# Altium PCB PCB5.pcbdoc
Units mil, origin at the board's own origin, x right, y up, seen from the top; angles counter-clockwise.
Board outline 7370 x 5003.1 mil, 2 copper layers (Top Layer, Bottom Layer); 30 components, 59 nets, 149 pads, 1 vias.
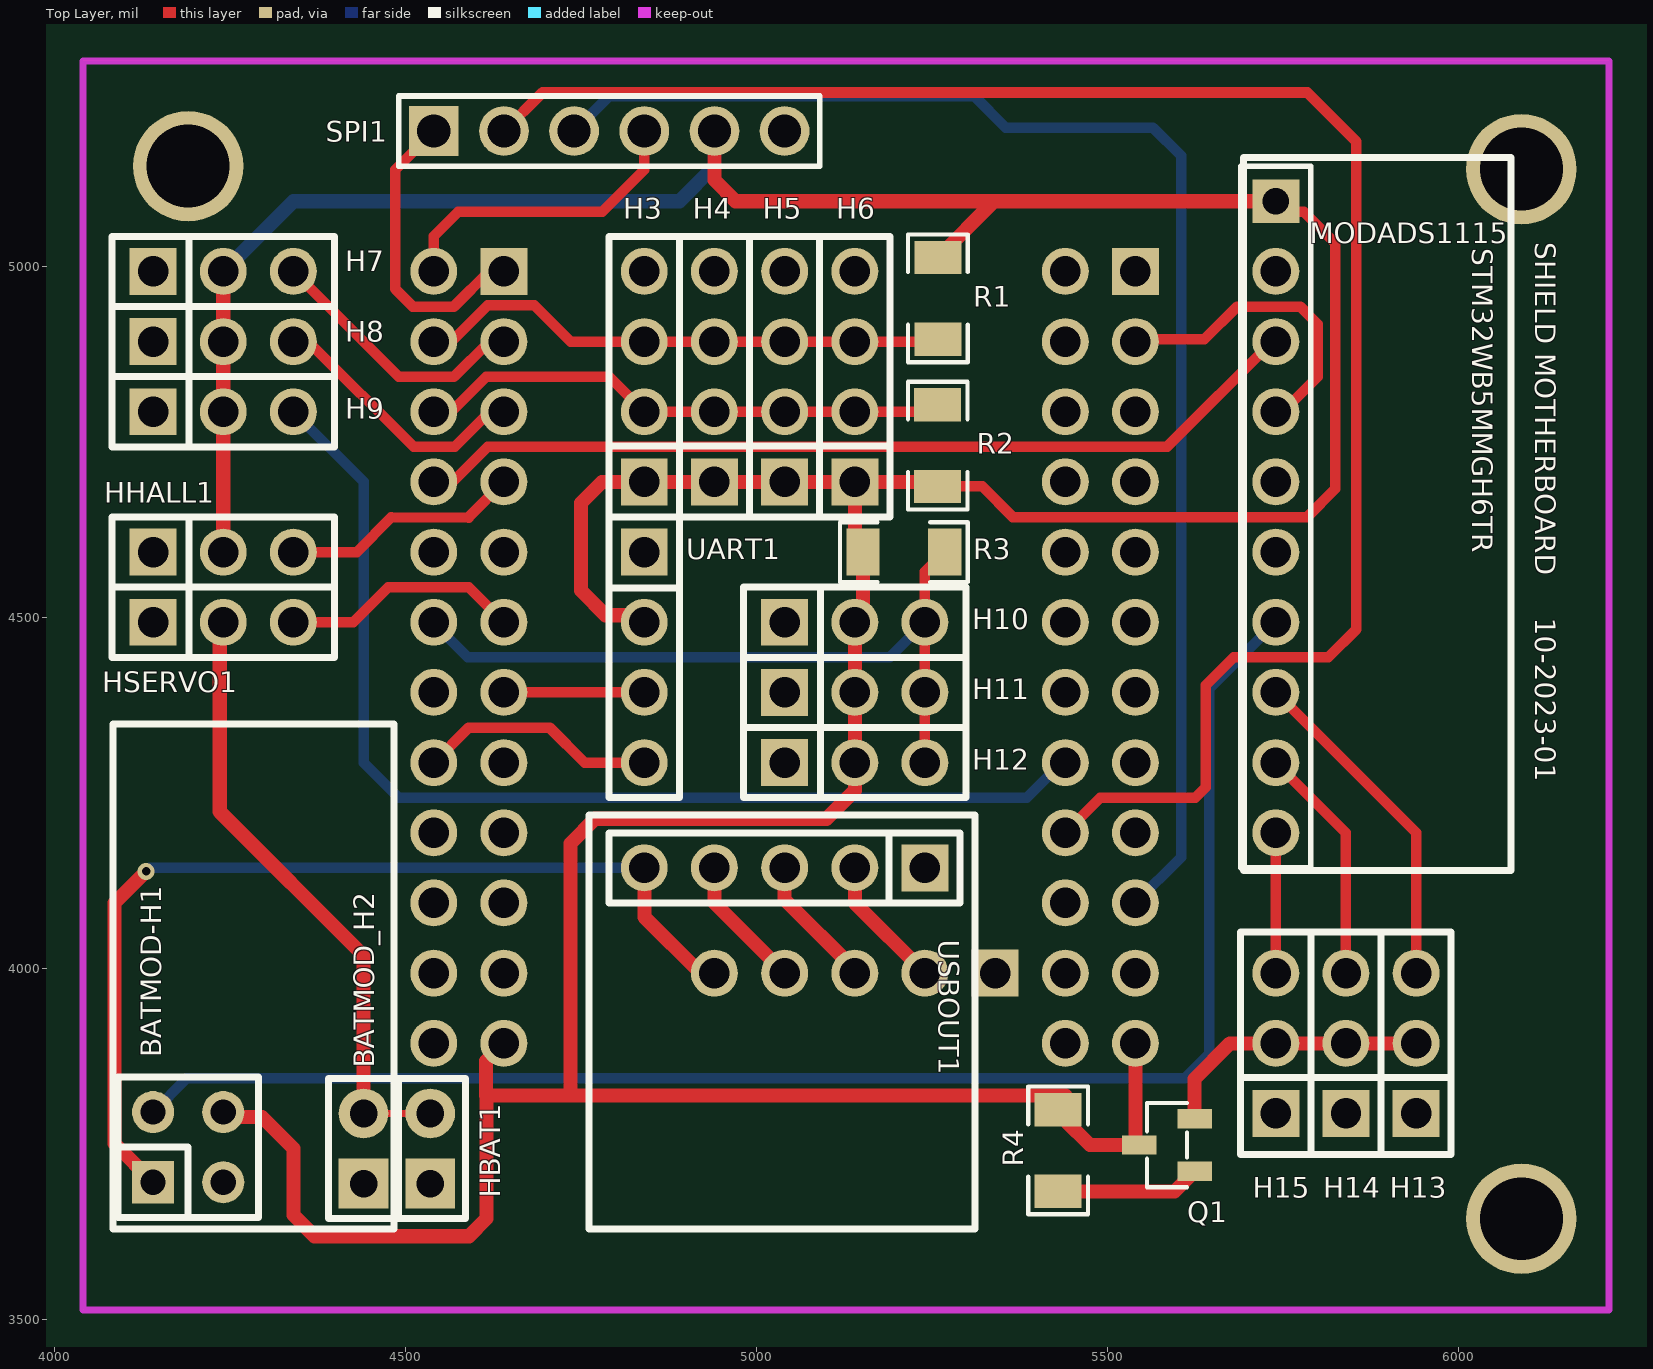
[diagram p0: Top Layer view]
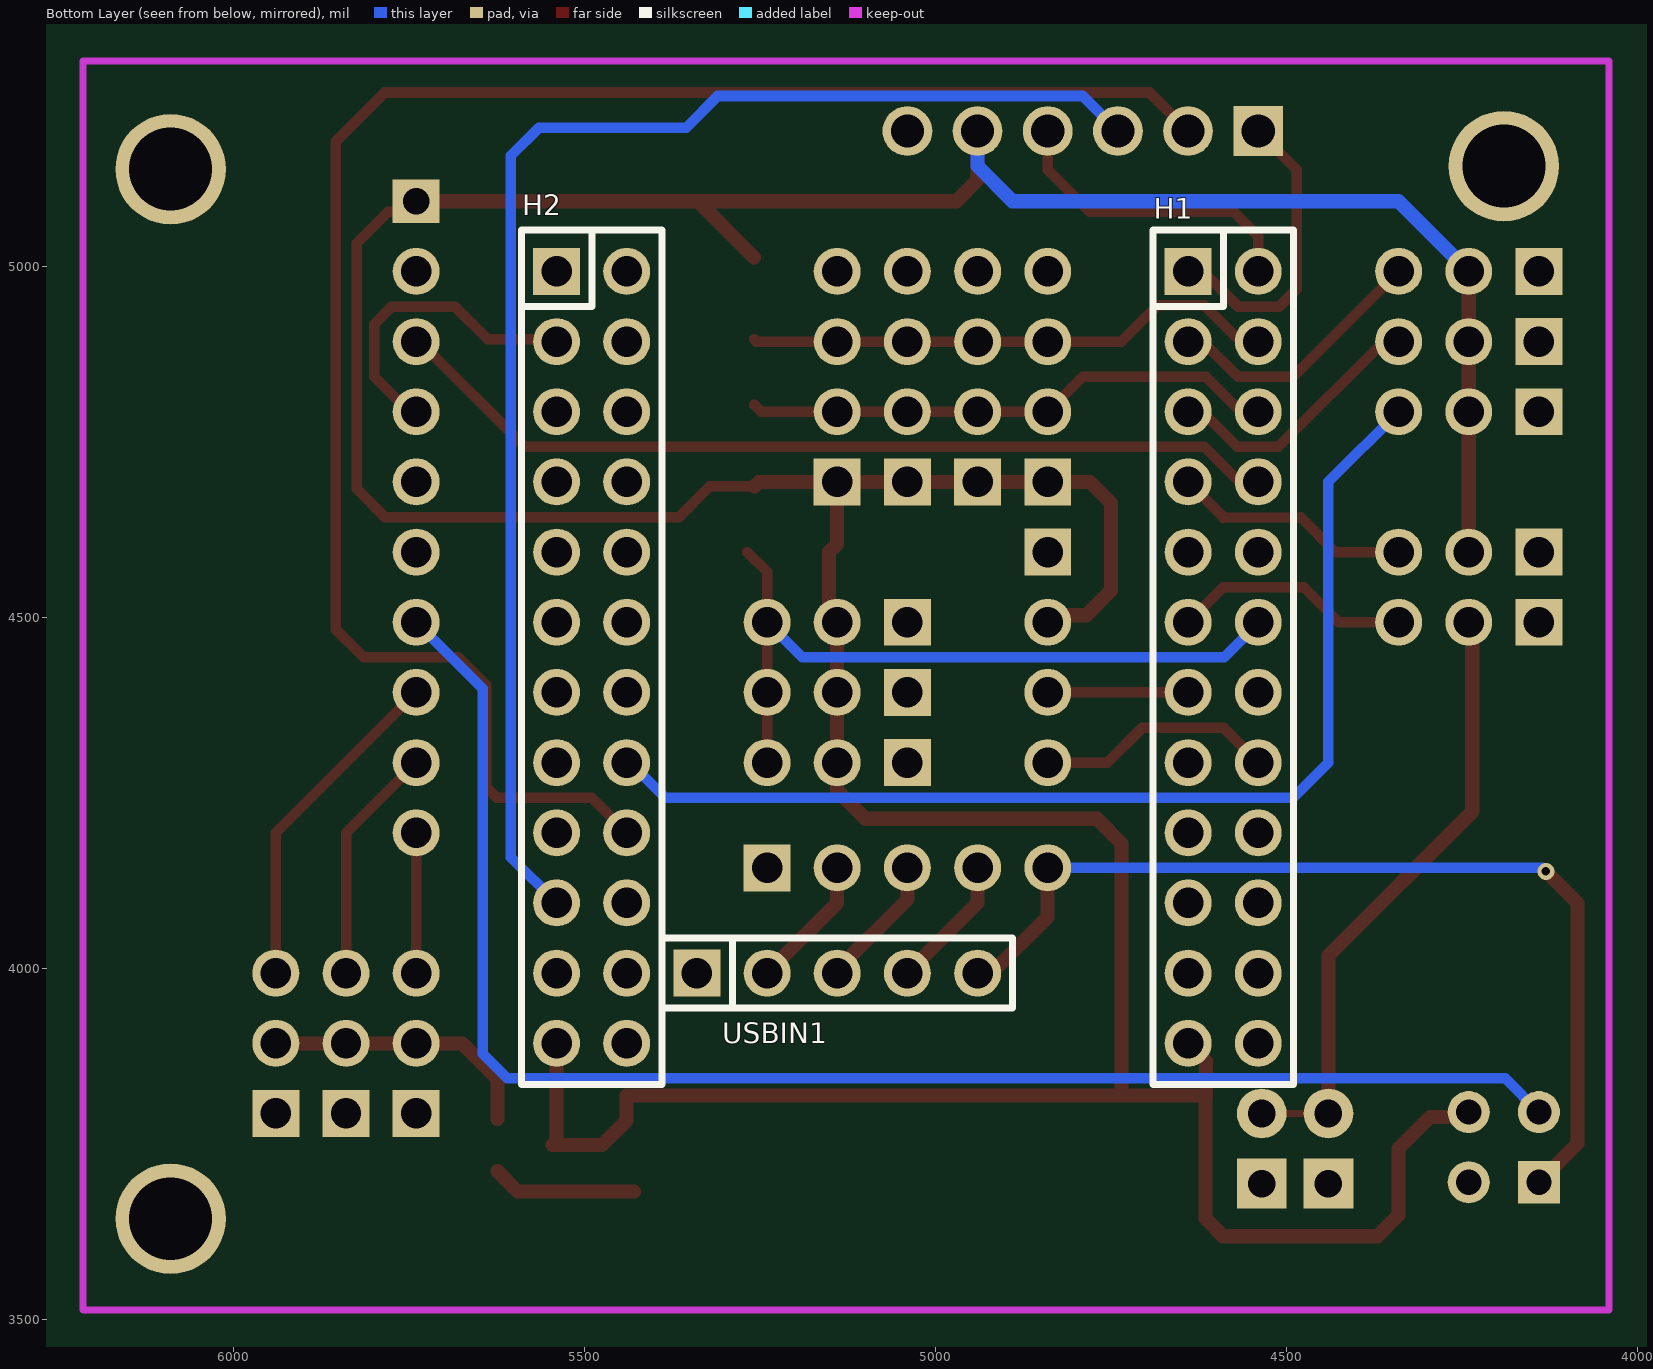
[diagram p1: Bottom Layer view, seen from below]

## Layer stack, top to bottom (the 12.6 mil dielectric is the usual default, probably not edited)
Top Layer: signal copper (thickness not stored)
Dielectric: dielectric 12.6, FR-4, Dk 4.8
Bottom Layer: signal copper (thickness not stored)

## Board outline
10120,2750 2750,2750 2750,7753.1 10120,7753.1

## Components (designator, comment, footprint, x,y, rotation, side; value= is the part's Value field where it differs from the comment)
BATMOD-H1 "HDR-M_2.54_2x2" HDR-TH_4P-P2.54-V-M-R2-C2-S2.54-1 4190,3745.01 r0 top
BATMOD_H2 "HDR-M_2.54_1x2P" HDR-TH_2P-P2.54-V-M-1 4440,3743.1 r90 top
H1 "PZ254-2-12-Z-8.5" HDR-TH_24P-P2.54-V-M-R2-C12-S2.54 4590,4443.1 r270 bottom
H2 "PZ254-2-12-Z-8.5" HDR-TH_24P-P2.54-V-M-R2-C12-S2.54 5490,4443.1 r270 bottom
H3 "HDR-M_2.54_1x4P" HDR-TH_4P-P2.54-V-M 4840,4843.1 r90 top
H4 "HDR-M_2.54_1x4P" HDR-TH_4P-P2.54-V-M 4940,4843.1 r90 top
H5 "HDR-M_2.54_1x4P" HDR-TH_4P-P2.54-V-M 5040,4843.11 r90 top
H6 "HDR-M_2.54_1x4P" HDR-TH_4P-P2.54-V-M 5140,4843.1 r90 top
H7 "HDR-M_2.54_1x3P" HDR-TH_3P-P2.54-V-M 4240,4993.1 r0 top
H8 "HDR-M_2.54_1x3P" HDR-TH_3P-P2.54-V-M 4240,4893.1 r0 top
H9 "HDR-M_2.54_1x3P" HDR-TH_3P-P2.54-V-M 4240,4793.1 r0 top
H10 "HDR-M_2.54_1x3P" HDR-TH_3P-P2.54-V-M 5140,4493.1 r0 top
H11 "HDR-M_2.54_1x3P" HDR-TH_3P-P2.54-V-M 5140,4393.1 r0 top
H12 "HDR-M_2.54_1x3P" HDR-TH_3P-P2.54-V-M 5140,4293.1 r0 top
H13 "HDR-M_2.54_1x3P" HDR-TH_3P-P2.54-V-M 5940,3893.1 r90 top
H14 "HDR-M_2.54_1x3P" HDR-TH_3P-P2.54-V-M 5840,3893.1 r90 top
H15 "HDR-M_2.54_1x3P" HDR-TH_3P-P2.54-V-M 5740,3893.1 r90 top
HBAT1 "HDR-M_2.54_1x2P" HDR-TH_2P-P2.54-V-M-1 4535,3743.1 r90 top
HHALL1 "HDR-M_2.54_1x3P" HDR-TH_3P-P2.54-V-M 4240,4593.1 r0 top
HSERVO1 "HDR-M_2.54_1x3P" HDR-TH_3P-P2.54-V-M 4240,4493.1 r0 top
MODADS1115 "HDR-M_2.54_1x10P" hdr-th_10p-p2.54-v-m-1 5740,4643.1 r270 top
Q1 "CJ2301" SOT-23-3_L2.9-W1.3-P1.90-LS2.4-BR 5585,3748.1 r0 top
R1 "Res_1206" R1206 5258.4,4954.64 r270 top
R2 "Res_1206" R1206 5258.22,4744.88 r90 top
R3 "Res_1206" R1206 5210,4593.1 r180 top
R4 "Res_1206" R1206 5429.84,3740.32 r90 top
SPI1 "HDR-M_2.54_1x6P" HDR-TH_6P-P2.54-V-M-1 4790,5193.1 r0 top
UART1 "HDR-M_2.54_1x4P" HDR-TH_4P-P2.54-V-M 4840,4443.1 r270 top
USBIN1 "HDR-M_2.54_1x5P" HDR-TH_5P-P2.54-V-M 5140,3993.1 r180 bottom
USBOUT1 "HDR-M_2.54_1x5P" HDR-TH_5P-P2.54-V-M 5040,4143.1 r180 top

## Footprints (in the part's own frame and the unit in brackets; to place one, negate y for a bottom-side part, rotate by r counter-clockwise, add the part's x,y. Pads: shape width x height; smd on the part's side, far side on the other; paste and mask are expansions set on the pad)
HDR-TH_2P-P2.54-V-M-1 [mm]
  rect 1.8x1.8 hole 1: 1(-1.27,0)
  round 1.8 hole 1: 2(1.27,0)
  silkscreen extent -2.54,-1.27 2.54,1.27
HDR-TH_3P-P2.54-V-M [mm]
  rect 1.7x1.7 hole 1.1: 1(-2.54,0)
  round 1.7 hole 1.1: 2(0,0) 3(2.54,0)
  silkscreen extent -4.02,-1.27 4.02,1.27
HDR-TH_4P-P2.54-V-M [mm]
  rect 1.7x1.7 hole 1.1: 1(-3.81,0)
  round 1.7 hole 1.1: 2(-1.27,0) 3(1.27,0) 4(3.81,0)
  silkscreen extent -5.08,-1.27 5.08,1.27
HDR-TH_4P-P2.54-V-M-R2-C2-S2.54-1 [mil]
  rect 60x60 hole 36: 1(-50,-50)
  round 60 hole 36: 2(-50,50) 3(50,-50) 4(50,50)
  silkscreen extent -100,-100 100,100
HDR-TH_5P-P2.54-V-M [mm]
  rect 1.7x1.7 hole 1.1: 1(-5.08,0)
  round 1.7 hole 1.1: 2(-2.54,0) 3(0,0) 4(2.54,0) 5(5.08,0)
  silkscreen extent -6.35,-1.27 6.35,1.27
HDR-TH_6P-P2.54-V-M-1 [mm]
  rect 1.8x1.8 hole 1.2: 1(-6.35,0)
  round 1.8 hole 1.2: 2(-3.81,0) 3(-1.27,0) 4(1.27,0) 5(3.81,0) 6(6.35,0)
  silkscreen extent -7.62,-1.27 7.62,1.27
hdr-th_10p-p2.54-v-m-1 [mm]
  rect 1.575x1.7 hole 0.945: 1(-11.43,0)
  round 1.7 hole 1.1: 2(-8.89,0) 3(-6.35,0) 4(-3.81,0) 5(-1.27,0) 6(1.27,0) 7(3.81,0) 8(6.35,0) 9(8.89,0) 10(11.43,0)
  silkscreen extent -12.7,-1.27 12.7,1.27
HDR-TH_24P-P2.54-V-M-R2-C12-S2.54 [mm]
  rect 1.7x1.7 hole 1.1: 1(-13.97,-1.27)
  round 1.7 hole 1.1: 2(-13.97,1.27) 3(-11.43,-1.27) 4(-11.43,1.27) 5(-8.89,-1.27) 6(-8.89,1.27) 7(-6.35,-1.27) 8(-6.35,1.27) 9(-3.81,-1.27) 10(-3.81,1.27) 11(-1.27,-1.27) 12(-1.27,1.27) 13(1.27,-1.27) 14(1.27,1.27) 15(3.81,-1.27) 16(3.81,1.27) 17(6.35,-1.27) 18(6.35,1.27) 19(8.89,-1.27) 20(8.89,1.27) 21(11.43,-1.27) 22(11.43,1.27) 23(13.97,-1.27) 24(13.97,1.27)
  silkscreen extent -15.47,-2.54 15.47,2.54
R1206 [mil]
  rect 47.54x66.97 smd: 1(-58.22,0) 2(58.22,0)
  silkscreen extent -91,-42 91,42
SOT-23-3_L2.9-W1.3-P1.90-LS2.4-BR [mm]
  rect 1.25x0.7 smd: 1(1,-0.95) 2(1,0.95) 3(-1,0)
  silkscreen extent -0.73,-1.53 0.73,1.53

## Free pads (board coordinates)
  round 157.48 hole 118.11: 1(4190,5143.1) 1(6090,3643.1)
  round 157.5 hole 118.11: 1(6090,5138.81)

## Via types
v1: diameter 24.02, hole 12.01, Top Layer to Bottom Layer, 1 vias

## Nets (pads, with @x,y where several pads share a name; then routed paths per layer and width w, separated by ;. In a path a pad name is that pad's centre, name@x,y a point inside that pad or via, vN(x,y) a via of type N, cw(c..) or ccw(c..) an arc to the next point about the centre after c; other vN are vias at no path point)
AIN1: H13.3 MODADS1115.8 | length 482.8
  Top Layer w15: MODADS1115.8 5940,4193.1 H13.3
AIN2: H14.3 MODADS1115.9 | length 341.4
  Top Layer w15: MODADS1115.9 5840,4193.1 H14.3
AIN3: H15.3 MODADS1115.10 | length 200
  Top Layer w15: H15.3 MODADS1115.10
ALERT: MODADS1115.6
BOOT0: H2.15
CMDVCAPT: Q1.1 R4.1 | length 206.4
  Top Layer w20: R4.1 5595.77,3682.1 Q1.1
D+: USBIN1.3 USBOUT1.3 | length 191.4
  Top Layer w20: USBOUT1.3 5040,4098.1 5140,3998.1 USBIN1.3
D-: USBIN1.4 USBOUT1.4 | length 191.4
  Top Layer w20: USBOUT1.4 4940,4093.1 USBIN1.4
GND: BATMOD-H1.3 BATMOD_H2.1 H1.24 H2.24 H3.4 H4.4 H5.4 H6.4 H7.1 H8.1 H9.1 H10.1 H11.1 H12.1 H13.1 H14.1 H15.1 HBAT1.1 HHALL1.1 HSERVO1.1 MODADS1115.2 MODADS1115.5 pad.1 SPI1.6 UART1.1 USBIN1.1 USBOUT1.1
I2C1_SCL: H1.8 MODADS1115.3 | length 1286.2
  Top Layer w15: H1.8 4544.02,4689.08 4562.88,4689.08 4616.89,4743.1 5585,4743.1 5735,4893.1 MODADS1115.3
I2C1_SDA: H2.3 MODADS1115.4 | length 446.8
  Top Layer w15: H2.3 5543.11,4896.21 5638.11,4896.21 5685,4943.1 5775,4943.1 5800,4918.1 5800,4843.1 5750,4793.1 MODADS1115.4
I2C3_SCL: H1.4 H3.3 H4.3 H5.3 H6.3 R1.2 | length 762.8
  Top Layer w15: H1.4 4565,4893.1 4616.95,4945.05 4683.05,4945.05 4735,4893.1 H3.3 H4.3 H5.3 H6.3 5255.07,4893.1 R1.2
I2C3_SDA: H1.6 H3.2 H4.2 H5.2 H6.2 R2.2 | length 763.8
  Top Layer w15: H1.6 4565,4793.1 4615,4843.1 4790,4843.1 H3.2 H4.2 H5.2 H6.2 5248.22,4793.1 R2.2
IO: USBIN1.2 USBOUT1.2 | length 191.4
  Top Layer w20: USBOUT1.2 5140,4093.1 USBIN1.2
LED: H2.21
LPTIM1_IN1: H2.1
LPTIM2_IN1: H2.16 H9.3 | length 1577.8
  Bottom Layer w15: H9.3 4440,4693.1 4440,4293.1 4490,4243.1 5385,4243.1 H2.16@5435,4293.1
LPUART1_RX: H1.16 UART1.4 | length 341.4
  Top Layer w15: H1.16 4590,4343.1 4705,4343.1 4755,4293.1 UART1.4
LPUART1_TX: H1.13 UART1.3 | length 205
  Top Layer w15: H1.13@4635,4393.1 UART1.3
NRST: H2.17
PA0: H2.22
PA1: H1.22
PA8: H1.17
PA15: H2.10
PB0/ONEWIRE: H1.12 H10.3 H11.3 H12.3 R3.1 | length 1053.9
  Top Layer w15: H12.3 H11.3 H10.3 5240,4564.88 R3.1
  Bottom Layer w15: H1.12 4540,4491.7 4588.6,4443.1 5190,4443.1 H10.3
PB1: H1.11 HSERVO1.3 | length 341.4
  Top Layer w15: HSERVO1.3 4425,4493.1 4475,4543.1 4590,4543.1 H1.11
PB2: H1.15
PB12: H1.10
PB15: H1.5 H8.3 | length 382.8
  Top Layer w15: H8.3 4361.21,4893.1 4511.21,4743.1 4570,4743.1 4620,4793.1 H1.5
PC1: H2.20
PC4: H1.18
PC5: H1.14
PC6: H1.3 H7.3 | length 382.8
  Top Layer w15: H7.3 4490,4843.1 4568.79,4843.1 4618.79,4893.1 H1.3
PC10: H2.5
PC11: H2.6
PC12: H2.7
PC13: H1.7 HHALL1.3 | length 342.4
  Top Layer w15: HHALL1.3 4430,4593.1 4479.47,4642.57 4590,4641.91 4590,4643.1 H1.7
PE4: H1.9
SPI1_CS: H1.21
SPI1_SCK: H1.20
SPI2_CS: H1.2 SPI1.4 | length 444.4
  Top Layer w15: H1.2 4540,5043.1 4575,5078.1 4780,5078.1 4840,5138.1 SPI1.4
SPI2_MISO: H2.18 SPI1.2 | length 2581.8
  Top Layer w15: SPI1.2 4695,5248.1 5785,5248.1 5855,5178.1 5855,4483.1 5815,4443.1 5680,4443.1 5640,4403.1 5640,4258.1 5625,4243.1 5490,4243.1 H2.18
SPI2_MOSI: H2.19 SPI1.3 | length 2012.8
  Bottom Layer w15: SPI1.3 4790,5243.1 5310,5243.1 5355,5198.1 5565,5198.1 5605,5158.1 5605,4158.1 H2.19
SPI2_SCK: H1.1 SPI1.1 | length 433.8
  Top Layer w15: SPI1.1 4485,5138.1 4485,4968.1 4510,4943.1 4568.79,4943.1 4618.79,4993.1 H1.1
SWDCK: H2.9
SWDIO: H2.8
USART1_CTS: H2.2
USART1_RTS: H2.4
USART1_RX: H2.11
USART1_TX: H1.19
USBN: H2.13
USBP: H2.12
VBAT: H2.14
VBAT_IN: BATMOD_H2.2 HBAT1.2 HSERVO1.2 | length 882
  Top Layer w10: BATMOD_H2.2 HBAT1.2
  Top Layer w20: HSERVO1.2 4235,4488.1 4235,4223.1 4440,4018.1 BATMOD_H2.2
VBUS: BATMOD-H1.1 USBIN1.5 USBOUT1.5 | length 1399.7
  Top Layer w20: v1(4130,4138.1) 4085,4093.1 4085,3750.01 BATMOD-H1.1 ; USBOUT1.5 4840,4073.1 4920,3993.1 USBIN1.5
  Bottom Layer w15: v1(4130,4138.1) 4135,4143.1 USBOUT1.5
VCAPT: H13.2 H14.2 H15.2 Q1.2 | length 393.6
  Top Layer w20: Q1.2 5624.37,3842.47 5675,3893.1 H15.2 H14.2 H13.2
VCC: BATMOD-H1.4 H1.23 H2.23 H3.1 H4.1 H5.1 H6.1 H7.2 H8.2 H9.2 H10.2 H11.2 H12.2 HHALL1.2 MODADS1115.1 Q1.3 R1.1 R2.1 R3.2 R4.2 SPI1.5 UART1.2 | length 7175.5
  Top Layer w15: R2.1 5321.44,4686.66 5365,4643.1 5785,4643.1 5825,4683.1 5825,5033.1 5780,5078.1 5755,5078.1 MODADS1115.1
  Top Layer w20: BATMOD-H1.4 4246.91,3788.1 4295,3788.1 4340,3743.1 4340,3648.1 4370,3618.1 4590,3618.1 4615,3643.1 4615,3818.1 4614.46,3818.64 ; HHALL1.2 H9.2 H8.2 H7.2 ; H1.23 4614.46,3867.56 4614.46,3818.64 ; UART1.2 4830,4503.1 4785,4503.1 4750,4538.1 4750,4663.1 4780,4693.1 H3.1 H4.1 H5.1 H6.1 ; SPI1.5 4940,5123.1 4970,5093.1 5338.63,5093.1 ; R2.1 5251.78,4693.1 H6.1 ; R1.1 5338.63,5093.1 ; H2.23 5540,3753.73 Q1.3 5475,3748.1 5440,3783.1 5440,3818.64 4735.95,3818.64 ; MODADS1115.1 5338.63,5093.1 ; 4614.46,3818.64 4735.95,3818.64 ; 4735.95,3818.64 4735,3819.59 4735,4178.1 4770,4213.1 5100,4213.1 5140,4253.1 H12.2 H11.2 H10.2 5151.78,4504.88 R3.2 5140,4604.88 H6.1
  Bottom Layer w20: H7.2 4340,5093.1 4890,5093.1 4940,5143.1 SPI1.5
VSENS: BATMOD-H1.2 MODADS1115.7 | length 2193.8
  Bottom Layer w15: BATMOD-H1.2 4188.09,3843.1 5610,3843.1 5645,3878.1 5645,4398.1 MODADS1115.7
"": 

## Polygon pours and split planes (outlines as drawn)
GND on Top Layer (solid, remove dead copper, pour order 0): 4040,3513.1 6215,3513.1 6215,5293.1 4040,5293.1
GND on Bottom Layer (solid, remove dead copper, pour order 1): 4040,3513.1 6215,3513.1 6215,5293.1 4040,5293.1

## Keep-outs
Board Outline Layer:
  lines w10 net "": 4040,3513.1 6215,3513.1 6215,5293.1 4040,5293.1 4040,3513.1

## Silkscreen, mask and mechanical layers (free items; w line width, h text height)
Top Silkscreen Layer:
  lines w10 net "": 4083.09,3628.1 4483.09,3628.1 4483.09,4348.1 4083.09,4348.1 4083.09,3628.1 ; 4761.45,3628.1 5311.45,3628.1 5311.45,4218.1 4761.45,4218.1 4761.45,3628.1 ; 5694,4139.17 6075,4139.17 6075,5155.17 5694,5155.17 5694,4139.17
  text "SHIELD MOTHERBOARD" at 6109.99,5034.83 h29.2 r270
  text "STM32WB5MMGH6TR" at 6019.99,5025.98 h29.2 r270
  text "10-2023-01" at 6109.99,4499.57 h29.2 r270
Mechanical Layer:
  lines w10 net "": 4440,3791.18 5640,3791.18 5640,5701.81 4440,5701.81 4440,3791.18
Mech6:
  text "STM32WB55MMG MB" at 4407.31,5814.74 h77.88
  text "SPI2_SCK /  SPI2_MISO /  SPI2_MOSI /  SPI2_CS /  VCC /  GND" at 5057.8,5229.82 h76.58 r90
  text "GND/VCC/PC6 /  GND/VCC/PB15 /  GND/VCC/LPTIM2_IN1" at 2866.61,4765.3 h74.53
  text "GND/GND/GND/GND /  SCL/SCL/SCL/SCL /  SDA/SDA/SDA/SDA /  VCC/VCC/VCC/VCC" at 6141.98,4680.3 h75.57
  text "GND/VCC/PC13 /  GND/VBATIN/PB1" at 3117.17,4460.3 h72.35
  text "GND/VCC/PB0 ONEWIRE /  GND/VCC/PB0 ONEWIRE /  GND/VCC/PB0 ONEWIRE" at 6778.94,4270.3 h74.53
  text "GND /  VCC /  LPUART1_TX /  LPUART1_RX" at 6182.91,4225.3 h75.57
  text "AIN3/AIN2/AIN1 /  VCAPT /  GND" at 6142.27,3770.3 h74.53
  text "USB VBUS /  D- /  D+ /  IO /  GND" at 5257.8,2936.94 h76.18 r90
